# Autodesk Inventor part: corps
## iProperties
Shininess: 79.0
Length Units: 11269
Angle Units: 11279
Time Units: 11290
Mass Units: 11283
Length Display Precision: 3
Angle Display Precision: 2
Created: 2002-03
Part Number: corps
Material: Par défaut
Document SubType Name: Modélisation
Designer: User
Density: 0.0
Volumn: 0.0
Area: 0.0
PropertySet Name: Model Information
Control State: 0
Master: False
Checked Out: False
Author: User
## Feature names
1. Extrusion1
2. Dépouille d'arête2
3. Dépouille d'arête3
4. Congé1 [Fillet]
5. Extrusion2
6. Dépouille d'arête4
7. Dépouille d'arête5
8. Extrusion4
9. Dépouille d'arête6
10. Dépouille d'arête7
11. Extrusion5
12. Symétrie1 [Mirror]
13. Extrusion6
14. Symétrie3 [Mirror]
15. Extrusion9
16. Dépouille d'arête8
17. Congé2 [Fillet]
18. Extrusion10
19. Perçage2 [Hole]
20. Extrusion11
21. Symétrie4 [Mirror]
22. Perçage3 [Hole]
23. Extrusion12
24. Chanfrein1 [Chamfer]
25. Extrusion13
26. Extrusion14
27. Extrusion15
28. Extrusion16
29. Extrusion17
30. Perçage4 [Hole]
31. Extrusion18
32. Extrusion19
33. Extrusion20
34. Extrusion21
35. Extrusion22
36. Symétrie5 [Mirror]
37. Extrusion23
38. Extrusion24
39. Perçage5 [Hole]
40. Extrusion25
41. Extrusion26
42. Extrusion27
43. Perçage6 [Hole]
